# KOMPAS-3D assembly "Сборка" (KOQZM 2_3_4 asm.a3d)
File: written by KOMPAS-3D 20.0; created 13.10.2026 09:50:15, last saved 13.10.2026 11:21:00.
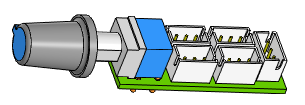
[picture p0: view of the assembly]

Document properties: Полное имя файла: D:\myProjects\Progect_esp32\box_compas\переключатели и кнопки\KOQZM 2_3_4 asm.a3d

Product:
- Part/product: Сборка
    Масса: 0.0398888
  - Component [detail]: Деталь  | qty 5  | Масса: 0.00117184; source file: ..\разъемы\B3B-XH-A.m3d
  - Component [detail]: Деталь  | Масса: 0.00708008; source file: KOQZM 2_3_4 pcb.m3d
  - Component [detail]: Деталь  | Масса: 0.0129423; source file: RS1010.m3d
  - Component [detail]: Деталь  | Масса: 0.0140072; source file: ..\ручки\ручка.m3d

Referenced files in D:\myProjects\Progect_esp32\box_compas\переключатели и кнопки\: KOQZM 2_3_4 pcb.m3d, RS1010.m3d
Referenced files in D:\myProjects\Progect_esp32\box_compas\разъемы\: B3B-XH-A.m3d
Referenced files in D:\myProjects\Progect_esp32\box_compas\ручки\: ручка.m3d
